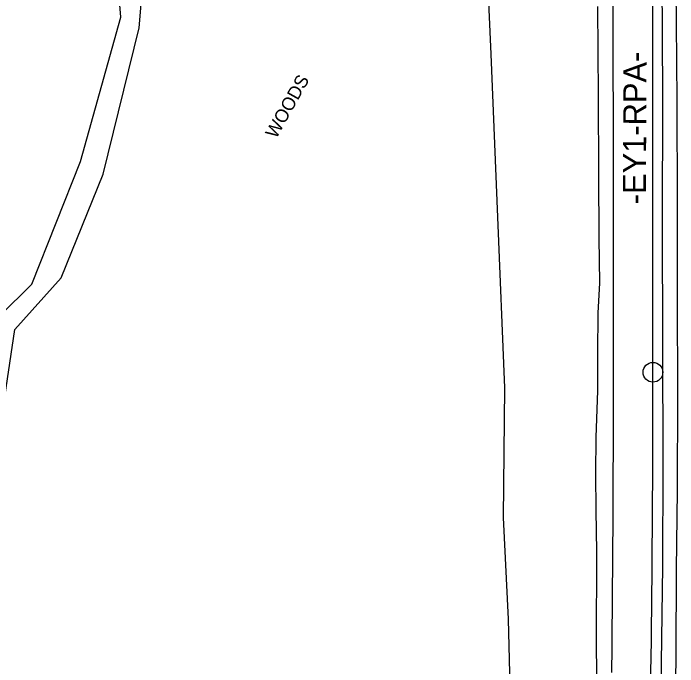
# Model space of a CAD drawing. Extents: x 2074109 to 2077820, y 741079 to 746031.
# Drawn here: x 2074923.4 to 2075124.8, y 743171.4 to 743369.7 of the extents above; entities that cross this region are included whole.
import ezdxf

# ---------------------------------------------------------------- set-up
doc = ezdxf.new("R2010")
doc.units = 0
for name, color, linetype in [('Exist Horizontal Alignment', 7, 'Continuous'), ('Exist Horizontal Alignment Direction Label', 7, 'Continuous'), ('Exist Horizontal Alignment Point', 7, 'Continuous'), ('Exist Hydro Jurisdictional Stream or Body of Water', 7, 'Continuous'), ('Exist Roads EOP', 7, 'Continuous'), ('Exist Roads EOT', 7, 'Continuous'), ('Exist Vegetation Woods Line', 7, 'Continuous'), ('Exist Vegetation Woods Line Text', 7, 'Continuous')]:
    doc.layers.add(name, color=color, linetype=linetype)

msp = doc.modelspace()

# ---------------------------------------------------------------- linework, layer by layer
at = {"layer": 'Exist Horizontal Alignment'}
msp.add_line((2075117.31, 743260.76), (2075117.13, 743617.06), dxfattribs=at)
msp.add_arc((2068655.86, 743257.58), 6461.45, 358.668924, 0.028253, dxfattribs=at)
at = {"layer": 'Exist Horizontal Alignment Point'}
msp.add_circle((2075117.31, 743260.76), 3, dxfattribs=at)
at = {"layer": 'Exist Hydro Jurisdictional Stream or Body of Water'}
for points in [[(2074903.25, 743054.49), (2074909.76, 743105.79), (2074914.28, 743166.15), (2074918.88, 743241.03), (2074923.86, 743273.74), (2074937.88, 743289.43), (2074950.67, 743320.84), (2074961.52, 743365.31), (2074962.73, 743379.75), (2074948.34, 743392.28), (2074946.95, 743398.74), (2074944.01, 743415.47), (2074942.43, 743425.27), (2074948.3, 743442.32)], [(2074900.6, 743092.38), (2074902.83, 743108.44), (2074909.01, 743167.83), (2074911.03, 743221.44), (2074912.87, 743241.26), (2074919.25, 743277.85), (2074929.03, 743287.53), (2074943.81, 743324.69), (2074955.99, 743368.53), (2074954.81, 743383.32), (2074937.89, 743386.14), (2074927.97, 743394.52), (2074919.08, 743396.01), (2074906.45, 743395.37), (2074895.43, 743399.83)]]:
    msp.add_lwpolyline(points, dxfattribs=at)
at = {"layer": 'Exist Roads EOP'}
for points in [[(2075124.08, 743150.18), (2075124.36, 743175.12), (2075124.47, 743200.9), (2075124.78, 743224.88), (2075124.82, 743253.79), (2075124.76, 743283.57), (2075124.75, 743311.89), (2075124.66, 743343.21), (2075124.49, 743366.69), (2075124.22, 743387.22)], [(2075100.46, 743371.73), (2075100.72, 743344.66), (2075100.79, 743320.73), (2075100.94, 743301.47), (2075101.1, 743287.9), (2075100.63, 743278.68), (2075100.47, 743266.6), (2075100.46, 743255.1), (2075100.02, 743241.03), (2075099.93, 743229.93), (2075099.96, 743218.83), (2075100.18, 743206.39), (2075100.18, 743195.53), (2075100.15, 743188.85), (2075100.06, 743177.57), (2075100.36, 743155.35)]]:
    msp.add_lwpolyline(points, dxfattribs=at)
at = {"layer": 'Exist Roads EOT'}
for points in [[(2075107.36, 742950.39), (2075109.71, 742970.82), (2075112.38, 742997.13), (2075114.36, 743020.92), (2075115.78, 743038.63), (2075117.18, 743060.58), (2075118.26, 743089.99), (2075119, 743113.88), (2075119.54, 743143.19), (2075119.9, 743172.64), (2075120.3, 743201.98), (2075120.44, 743232.24), (2075120.36, 743270.24), (2075120.21, 743304.86), (2075120.36, 743344.86), (2075120.15, 743380.31), (2075120.28, 743417.16), (2075120.24, 743451.73)], [(2075105.15, 743372.12), (2075105.16, 743369.62), (2075105.16, 743367.12), (2075105.17, 743364.62), (2075105.17, 743362.12), (2075105.18, 743359.62), (2075105.18, 743357.13), (2075105.19, 743354.63), (2075105.19, 743352.13), (2075105.2, 743349.63), (2075105.2, 743347.13), (2075105.21, 743344.63), (2075105.21, 743342.13), (2075105.21, 743339.63), (2075105.22, 743337.13), (2075105.23, 743334.63), (2075105.23, 743332.13), (2075105.24, 743329.63), (2075105.25, 743327.13), (2075105.26, 743324.64), (2075105.26, 743322.14), (2075105.27, 743319.64), (2075105.28, 743317.14), (2075105.28, 743314.64), (2075105.29, 743312.14), (2075105.29, 743309.64), (2075105.29, 743307.14), (2075105.29, 743304.64), (2075105.3, 743302.14), (2075105.3, 743299.64), (2075105.3, 743297.14), (2075105.3, 743294.64), (2075105.3, 743292.14), (2075105.3, 743289.64), (2075105.3, 743287.15), (2075105.3, 743284.65), (2075105.3, 743282.15), (2075105.29, 743279.65), (2075105.29, 743277.15), (2075105.29, 743274.65), (2075105.29, 743272.15), (2075105.29, 743269.65), (2075105.29, 743267.15), (2075105.29, 743264.65), (2075105.29, 743262.15), (2075105.29, 743259.65), (2075105.28, 743257.15), (2075105.27, 743254.65), (2075105.27, 743252.16), (2075105.26, 743249.66), (2075105.26, 743247.16), (2075105.25, 743244.66), (2075105.24, 743242.16), (2075105.24, 743239.66), (2075105.23, 743237.16), (2075105.22, 743234.66), (2075105.2, 743232.16), (2075105.19, 743229.66), (2075105.18, 743227.16), (2075105.17, 743224.67), (2075105.16, 743222.17), (2075105.15, 743219.67), (2075105.14, 743217.17), (2075105.13, 743214.67), (2075105.12, 743212.17), (2075105.1, 743209.67), (2075105.08, 743207.17), (2075105.06, 743204.67), (2075105.04, 743202.17), (2075105.02, 743199.68), (2075105, 743197.18), (2075104.98, 743194.68), (2075104.96, 743192.18), (2075104.94, 743189.68), (2075104.92, 743187.18), (2075104.9, 743184.68), (2075104.88, 743182.18), (2075104.86, 743179.68), (2075104.84, 743177.18), (2075104.82, 743174.68), (2075104.8, 743172.19), (2075104.79, 743169.69)]]:
    msp.add_lwpolyline(points, dxfattribs=at)
at = {"layer": 'Exist Vegetation Woods Line'}
for points in [[(2074905.1, 743624.9), (2074958.77, 743586.73), (2074978.04, 743573.88), (2074995.23, 743556.58), (2075005.25, 743550.04), (2075020.25, 743543.63), (2075030.01, 743537.15), (2075038.16, 743526.18), (2075053.34, 743511.04), (2075063.92, 743504.02), (2075066.65, 743499.3), (2075067.63, 743486.43), (2075064.69, 743471.93), (2075068.31, 743459.01), (2075075.3, 743432.9), (2075075.94, 743409.67), (2075071.68, 743391.87), (2075067.29, 743377.76), (2075068.15, 743357.32)], [(2075068.15, 743357.32), (2075070.2, 743307.84), (2075072.28, 743256.05), (2075071.95, 743216.75), (2075073.39, 743185.9), (2075074.89, 743128.72), (2075072.65, 743060.65), (2075071.29, 743012.69), (2075062.91, 742960.15), (2075044.76, 742889.65)]]:
    msp.add_lwpolyline(points, dxfattribs=at)

# ---------------------------------------------------------------- texts
at = {"layer": 'Exist Horizontal Alignment Direction Label'}
msp.add_text('-EY1-RPA-', height=7, rotation=89.7497, dxfattribs=at).set_placement((2075115.18, 743311.74))
at = {"layer": 'Exist Vegetation Woods Line Text'}
msp.add_text('WOODS', height=4, rotation=60.742, dxfattribs=at).set_placement((2075003.1, 743331.42))

doc.saveas('drawing.dxf')
